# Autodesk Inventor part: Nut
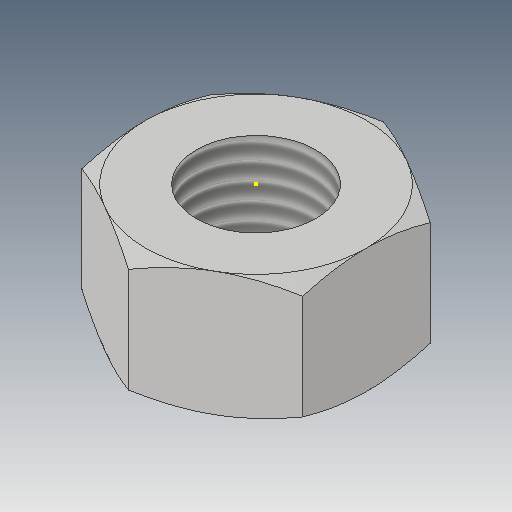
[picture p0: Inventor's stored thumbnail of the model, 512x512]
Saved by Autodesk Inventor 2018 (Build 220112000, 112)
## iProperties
Created: 2016-05
Part Number: Nut
Material: Generic
Document SubType Name: Modeling
Designer: CADCIM
Density: 1 g/cm^3
Appearance: Default
Author: CADCIM
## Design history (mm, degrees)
sketch "Sketch1"
  geometry: L1 (9.6, -5.543)-(0, -11.085); L2 (0, -11.085)-(-9.6, -5.543); L3 (-9.6, -5.543)-(-9.6, 5.543); L4 (-9.6, 5.543)-(0, 11.085); L5 (0, 11.085)-(9.6, 5.543); L6 (9.6, 5.543)-(9.6, -5.543); 2 further points
  constraints: 12 end point, 1 coincident, 1 vertical alignment, 13 other
  dimensions: "d0" = 19.2 distance between parallel lines of L3 L6
extrude "Extrusion1" new body sketch "Sketch1" distance "d1" = 10.8; taper "d2" = 0 deg
sketch "Sketch2"
  geometry: L1 (0, 11.085)-(-9.6, 5.543) reference; C1 r 9.6 at (0, 0); 1 further point
  constraints: 1 centre point, 1 coincident, 1 tangent
extrude "Extrusion2" sketch "Sketch2" distance "d3" = 10.8; taper "d4" = 60 deg
workplane "Work Plane1"
sketch "Sketch3"
  geometry: L1 (0, -11.085)-(9.6, -5.543) reference; C1 r 9.6 at (0, 0); 1 further point
  constraints: 1 centre point, 1 coincident, 1 tangent
extrude "Extrusion3" sketch "Sketch3" distance "d5" = 10.8; taper "d6" = 60 deg
sketch "Sketch4"
  geometry: 1 further point
hole "Hole1" diameter "d9" = 10.376; stored, may be unused: countersink angle "d13" = 90 deg, drill point angle "d15" = 118 deg; dims "d7" = 10, "d8" = 10, "d10" = 24, "d11" = 4, "d12" = 2, "d14" = 31.3
body "Solid1"
